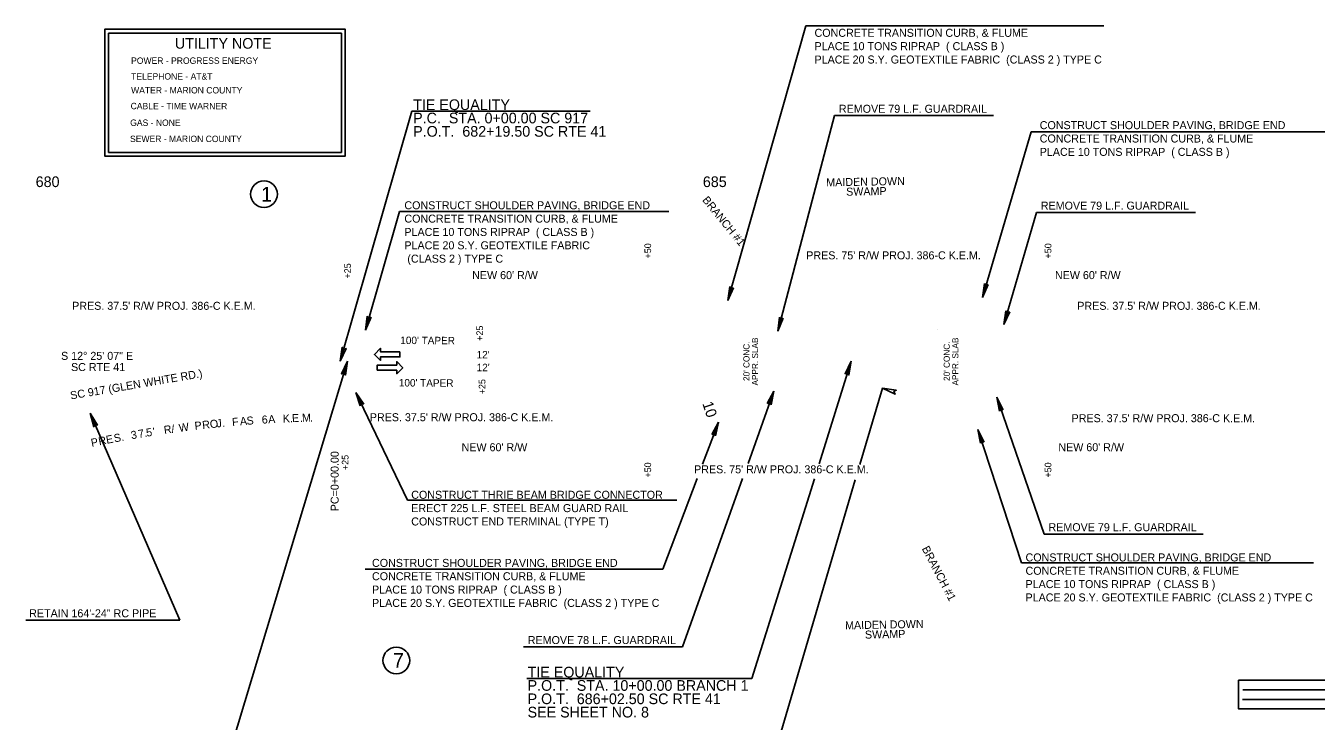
# Model space of a CAD drawing. Extents: x 2522404 to 2525275, y 885432 to 893540.
# Drawn here: x 2523396 to 2524364, y 888336 to 888857 of the extents above; entities that cross this region are included whole.
import ezdxf

# ---------------------------------------------------------------- set-up
doc = ezdxf.new("R2010")
doc.units = 0
for name, color, linetype in [('Default', 7, 'Continuous'), ('RD_DDB_Profile_EX', 7, 'Continuous'), ('RD_DDB_Profile_Lbl', 7, 'Continuous'), ('RD_DDB_StaTX', 7, 'Continuous'), ('RD_EV_JW', 7, 'Continuous'), ('RD_EX_H2O', 7, 'Continuous'), ('RD_EX_Misc', 7, 'Continuous'), ('RD_HC_Cl', 7, 'Continuous'), ('RD_HY_TX1', 7, 'Continuous'), ('RD_PD_Final_LnLine', 7, 'Continuous'), ('RD_PD_RW_TX', 7, 'Continuous'), ('RD_SHT_IplotShp', 7, 'Continuous'), ('RD_SHT_MnGrid', 7, 'Continuous'), ('RD_Sketch1', 7, 'Continuous')]:
    doc.layers.add(name, color=color, linetype=linetype)

# ---------------------------------------------------------------- blocks, each defined once
blk = doc.blocks.new('ah_')
at = {"layer": 'Default'}
blk.add_lwpolyline([(0, 0), (-1.45, -10.39), (0.04, -8.79), (1.55, -10.38)], close=True, dxfattribs=at)
blk = doc.blocks.new('ah4')
at = {"layer": 'Default', "rotation": -90.00000000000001}
blk.add_blockref('ah_', (0, 0), dxfattribs=at)
blk = doc.blocks.new('AH4_')
at = {"layer": 'Default'}
blk.add_lwpolyline([(0, 0), (-10.39, 1.5), (-8.79, 0), (-10.39, -1.5)], close=True, dxfattribs=at)
blk = doc.blocks.new('AH')
at = {"layer": 'Default'}
blk.add_lwpolyline([(0, 0), (-10.39, 1.5), (-8.79, 0), (-10.39, -1.5)], close=True, dxfattribs=at)

msp = doc.modelspace()

# ---------------------------------------------------------------- linework, layer by layer
at = {"layer": 'Default'}
for points in [[(2523676.88, 888612.66), (2523676.88, 888608.84), (2523662.27, 888608.84), (2523662.27, 888606.25), (2523657.77, 888610.75), (2523662.27, 888615.26), (2523662.27, 888612.66)], [(2523659.82, 888598.85), (2523659.82, 888602.67), (2523674.43, 888602.67), (2523674.43, 888605.26), (2523678.93, 888600.76), (2523674.43, 888596.25), (2523674.43, 888598.85)], [(2524305.29, 888366.47), (2524497.8, 888366.47), (2524497.8, 888345.08), (2524305.29, 888345.08)]]:
    msp.add_lwpolyline(points, close=True, dxfattribs=at)
at = {"layer": 'RD_DDB_StaTX'}
for p, q in [((2523922.69, 888651.1), (2523981.2, 888856.99)), ((2524204.41, 888856.99), (2523981.2, 888856.99)), ((2523960.05, 888628.2), (2524002.59, 888789.64)), ((2524113.39, 888653.47), (2524150.02, 888777.41)), ((2524373.22, 888777.41), (2524150.02, 888777.41)), ((2523676.58, 888717.91), (2523650.96, 888628.97)), ((2523878.52, 888717.91), (2523676.58, 888717.91)), ((2524129.55, 888633.06), (2524153.92, 888717.04)), ((2523924.09, 888661.5), (2523922.69, 888651.1)), ((2523924.09, 888661.5), (2523922.69, 888651.1)), ((2523922.69, 888651.1), (2523926.97, 888660.68)), ((2523922.69, 888651.1), (2523926.97, 888660.68)), ((2523925.09, 888659.55), (2523924.09, 888661.5)), ((2523925.09, 888659.55), (2523924.09, 888661.5)), ((2523926.97, 888660.68), (2523925.09, 888659.55)), ((2523926.97, 888660.68), (2523925.09, 888659.55)), ((2524114.89, 888663.85), (2524113.39, 888653.47)), ((2524114.89, 888663.85), (2524113.39, 888653.47)), ((2524113.39, 888653.47), (2524117.77, 888663)), ((2524113.39, 888653.47), (2524117.77, 888663)), ((2524115.88, 888661.89), (2524114.89, 888663.85)), ((2524115.88, 888661.89), (2524114.89, 888663.85)), ((2524117.77, 888663), (2524115.88, 888661.89)), ((2524117.77, 888663), (2524115.88, 888661.89)), ((2523652.39, 888639.36), (2523650.96, 888628.97)), ((2523652.39, 888639.36), (2523650.96, 888628.97)), ((2523653.39, 888637.41), (2523652.39, 888639.36)), ((2523653.39, 888637.41), (2523652.39, 888639.36)), ((2524131, 888643.46), (2524129.55, 888633.06)), ((2524131, 888643.46), (2524129.55, 888633.06)), ((2524129.55, 888633.06), (2524133.88, 888642.62)), ((2524129.55, 888633.06), (2524133.88, 888642.62)), ((2524132, 888641.5), (2524131, 888643.46)), ((2524132, 888641.5), (2524131, 888643.46)), ((2524133.88, 888642.62), (2524132, 888641.5)), ((2524133.88, 888642.62), (2524132, 888641.5)), ((2523650.96, 888628.97), (2523655.27, 888638.53)), ((2523650.96, 888628.97), (2523655.27, 888638.53)), ((2523655.27, 888638.53), (2523653.39, 888637.41)), ((2523655.27, 888638.53), (2523653.39, 888637.41)), ((2523961.25, 888638.63), (2523960.05, 888628.2)), ((2523961.25, 888638.63), (2523960.05, 888628.2)), ((2523960.05, 888628.2), (2523964.14, 888637.86)), ((2523960.05, 888628.2), (2523964.14, 888637.86)), ((2523962.29, 888636.7), (2523961.25, 888638.63)), ((2523962.29, 888636.7), (2523961.25, 888638.63)), ((2523964.14, 888637.86), (2523962.29, 888636.7)), ((2523964.14, 888637.86), (2523962.29, 888636.7)), ((2523682.46, 888501.41), (2523643.89, 888582.12)), ((2523643.89, 888582.12), (2523647.02, 888572.11)), ((2523649.72, 888573.4), (2523643.89, 888582.12)), ((2523643.89, 888582.12), (2523647.02, 888572.11)), ((2523649.72, 888573.4), (2523643.89, 888582.12)), ((2523957.1, 888583.12), (2523937.78, 888529.02)), ((2523957.1, 888583.12), (2523952.21, 888573.83)), ((2523957.1, 888583.12), (2523952.21, 888573.83)), ((2523955.04, 888572.83), (2523957.1, 888583.12)), ((2523955.04, 888572.83), (2523957.1, 888583.12)), ((2524038.47, 888585.31), (2524021.59, 888528.18)), ((2523647.02, 888572.11), (2523647.68, 888574.2)), ((2523647.02, 888572.11), (2523647.68, 888574.2)), ((2523647.68, 888574.2), (2523649.72, 888573.4)), ((2523647.68, 888574.2), (2523649.72, 888573.4)), ((2523952.21, 888573.83), (2523954.16, 888574.84)), ((2523952.21, 888573.83), (2523954.16, 888574.84)), ((2523954.16, 888574.84), (2523955.04, 888572.83)), ((2523954.16, 888574.84), (2523955.04, 888572.83)), ((2524124.22, 888578.58), (2524159.68, 888476.02)), ((2524124.22, 888578.58), (2524126.2, 888568.27)), ((2524129.04, 888569.25), (2524124.22, 888578.58)), ((2524124.22, 888578.58), (2524126.2, 888568.27)), ((2524129.04, 888569.25), (2524124.22, 888578.58)), ((2524126.2, 888568.27), (2524127.1, 888570.27)), ((2524126.2, 888568.27), (2524127.1, 888570.27)), ((2524127.1, 888570.27), (2524129.04, 888569.25)), ((2524127.1, 888570.27), (2524129.04, 888569.25)), ((2523915.5, 888559.62), (2523903.73, 888528.44)), ((2523915.59, 888559.85), (2523910.52, 888550.66)), ((2523915.59, 888559.85), (2523910.52, 888550.66)), ((2523913.32, 888549.61), (2523915.59, 888559.85)), ((2523913.32, 888549.61), (2523915.59, 888559.85)), ((2524110.05, 888554.4), (2524142.77, 888454.59)), ((2524110.05, 888554.4), (2524111.86, 888544.06)), ((2524114.71, 888545), (2524110.05, 888554.4)), ((2524110.05, 888554.4), (2524111.86, 888544.06)), ((2524114.71, 888545), (2524110.05, 888554.4)), ((2523910.52, 888550.66), (2523912.48, 888551.63)), ((2523910.52, 888550.66), (2523912.48, 888551.63)), ((2523912.48, 888551.63), (2523913.32, 888549.61)), ((2523912.48, 888551.63), (2523913.32, 888549.61)), ((2524111.86, 888544.06), (2524112.79, 888546.05)), ((2524111.86, 888544.06), (2524112.79, 888546.05)), ((2524112.79, 888546.05), (2524114.71, 888545)), ((2524112.79, 888546.05), (2524114.71, 888545)), ((2523899.67, 888517.67), (2523874.02, 888449.71)), ((2523933.73, 888517.68), (2523888.63, 888391.44)), ((2524018.16, 888516.59), (2523961.24, 888323.94)), ((2523884.39, 888501.41), (2523682.46, 888501.41)), ((2523874.02, 888449.71), (2523650.82, 888449.71)), ((2524361.62, 888454.59), (2524142.77, 888454.59))]:
    msp.add_line(p, q, dxfattribs=at)
for points in [[(2524121.81, 888789.64), (2524002.59, 888789.64)], [(2524273.13, 888717.04), (2524153.92, 888717.04)], [(2524278.9, 888476.02), (2524159.68, 888476.02)], [(2523888.63, 888391.44), (2523769.42, 888391.44)]]:
    msp.add_lwpolyline(points, dxfattribs=at)
at = {"layer": 'RD_EV_JW'}
msp.add_line((2524308.27, 888351.99), (2524383.17, 888351.99), dxfattribs=at)
at = {"layer": 'RD_EX_H2O'}
msp.add_line((2524382.98, 888359.41), (2524308.55, 888359.41), dxfattribs=at)
at = {"layer": 'RD_EX_Misc'}
for points in [[(2523471.74, 888759.33), (2523455.67, 888759.33), (2523455.67, 888854.37), (2523635.89, 888854.37), (2523635.89, 888759.33), (2523471.74, 888759.33)], [(2523474.65, 888762.08), (2523458.57, 888762.08), (2523458.57, 888851.46), (2523632.99, 888851.46), (2523632.99, 888762.08), (2523474.65, 888762.08)]]:
    msp.add_lwpolyline(points, dxfattribs=at)
for centre in [(2523575, 888730.79), (2523674.17, 888381.31)]:
    msp.add_circle(centre, 10, dxfattribs=at)
at = {"layer": 'RD_HC_Cl'}
msp.add_line((2524080.12, 888629.12), (2524080.12, 888629.12), dxfattribs=at)
at = {"layer": 'RD_HY_TX1'}
for points in [[(2523444.63, 888566.61), (2523511.85, 888411.59)], [(2523511.85, 888411.59), (2523396.48, 888411.59)]]:
    msp.add_lwpolyline(points, dxfattribs=at)
at = {"layer": 'RD_PD_RW_TX'}
for p, q in [((2523632.12, 888605.62), (2523685.82, 888793.08)), ((2523685.82, 888793.08), (2523819.36, 888793.08)), ((2524015.12, 888605.61), (2523990.95, 888528.61)), ((2523987.47, 888517.53), (2523940.49, 888367.86)), ((2523771.89, 888367.86), (2523940.49, 888367.86))]:
    msp.add_line(p, q, dxfattribs=at)
at = {"layer": 'RD_SHT_MnGrid'}
msp.add_line((2523546.05, 888301.87), (2523637.62, 888605.62), dxfattribs=at)

# ---------------------------------------------------------------- block references
at = {"layer": 'RD_HY_TX1', "rotation": 113.16953356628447}
msp.add_blockref('ah4', (2523444.63, 888566.61), dxfattribs=at)
at = {"layer": 'RD_PD_Final_LnLine'}
for p, rotation in [((2523632.12, 888605.62), -106.25802464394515), ((2523637.62, 888605.62), 72.95136999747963), ((2524015.12, 888605.61), 72.29836329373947)]:
    msp.add_blockref('AH4_', p, dxfattribs=dict(at, rotation=rotation))
at = {"layer": 'RD_PD_Final_LnLine', "yscale": -0.9999999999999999, "rotation": 163.81043232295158}
msp.add_blockref('AH', (2524038.47, 888585.31), dxfattribs=at)

# ---------------------------------------------------------------- texts
at = {"layer": 'RD_DDB_Profile_EX'}
for s, height, rotation, p in [('680', 8, 360, (2523403.89, 888736.12)), ('685', 8, 360, (2523903.92, 888736.12)), ("20' CONC.", 4.605, 90, (2523938.85, 888590.79)), ('APPR. SLAB', 4.605, 90, (2523945.3, 888587.39)), ("20' CONC.", 4.605, 90, (2524088.95, 888590.79)), ('APPR. SLAB', 4.605, 90, (2524095.4, 888587.39)), ('10', 8, 288.69992, (2523903.39, 888573.91))]:
    msp.add_text(s, height=height, rotation=rotation, dxfattribs=at).set_placement(p)
at = {"layer": 'RD_DDB_Profile_Lbl'}
for s, p in [('1', (2523572.87, 888725.29)), ('7', (2523671.65, 888375.81))]:
    msp.add_text(s, height=11, dxfattribs=at).set_placement(p)
at = {"layer": 'RD_DDB_StaTX'}
for s, p in [('CONCRETE TRANSITION CURB, & FLUME', (2523987.6, 888848.73)), ('PLACE 10 TONS RIPRAP  ( CLASS B )', (2523987.6, 888838.73)), ('PLACE 20 S.Y. GEOTEXTILE FABRIC  (CLASS 2 ) TYPE C', (2523987.6, 888828.73)), ('REMOVE 79 L.F. GUARDRAIL', (2524005.86, 888791.81)), ('CONSTRUCT SHOULDER PAVING, BRIDGE END', (2524156.38, 888779.52)), ('CONCRETE TRANSITION CURB, & FLUME', (2524156.38, 888769.52)), ('PLACE 10 TONS RIPRAP  ( CLASS B )', (2524156.38, 888759.52)), ('CONSTRUCT SHOULDER PAVING, BRIDGE END', (2523680.21, 888719.47)), ('REMOVE 79 L.F. GUARDRAIL', (2524157.19, 888719.2)), ('CONCRETE TRANSITION CURB, & FLUME', (2523680.21, 888709.47)), ('PLACE 10 TONS RIPRAP  ( CLASS B )', (2523680.21, 888699.47)), ('PLACE 20 S.Y. GEOTEXTILE FABRIC ', (2523680.21, 888689.47)), (' (CLASS 2 ) TYPE C', (2523680.21, 888679.47)), ('CONSTRUCT THRIE BEAM BRIDGE CONNECTOR', (2523685.33, 888502.49)), ('ERECT 225 L.F. STEEL BEAM GUARD RAIL', (2523685.33, 888492.49)), ('CONSTRUCT END TERMINAL (TYPE T)', (2523685.33, 888482.49)), ('REMOVE 79 L.F. GUARDRAIL', (2524162.96, 888478.18)), ('CONSTRUCT SHOULDER PAVING, BRIDGE END', (2523655.95, 888451.43)), ('CONSTRUCT SHOULDER PAVING, BRIDGE END', (2524145.74, 888455.54)), ('CONCRETE TRANSITION CURB, & FLUME', (2523655.95, 888441.43)), ('CONCRETE TRANSITION CURB, & FLUME', (2524145.74, 888445.54)), ('PLACE 10 TONS RIPRAP  ( CLASS B )', (2523655.95, 888431.43)), ('PLACE 10 TONS RIPRAP  ( CLASS B )', (2524145.74, 888435.54)), ('PLACE 20 S.Y. GEOTEXTILE FABRIC  (CLASS 2 ) TYPE C', (2523655.95, 888421.43)), ('PLACE 20 S.Y. GEOTEXTILE FABRIC  (CLASS 2 ) TYPE C', (2524145.74, 888425.54)), ('REMOVE 78 L.F. GUARDRAIL', (2523772.69, 888393.6))]:
    msp.add_text(s, height=6, dxfattribs=at).set_placement(p)
for s, p in [("100' TAPER", (2523677.12, 888618.51)), ("12'", (2523734.33, 888607.74)), ("12'", (2523734.36, 888598.13)), ("100' TAPER", (2523676.03, 888586.68))]:
    msp.add_text(s, height=5.6, rotation=359.58606, dxfattribs=at).set_placement(p)
at = {"layer": 'RD_EX_Misc'}
for s, height, p in [('UTILITY NOTE', 8, (2523508.19, 888839.83)), ('POWER - PROGRESS ENERGY', 4.8, (2523475.39, 888828.48)), ('TELEPHONE - AT&T', 4.8, (2523475.39, 888816.68)), ('WATER - MARION COUNTY', 4.8, (2523475.39, 888806.29)), ('CABLE - TIME WARNER', 4.8, (2523475.04, 888794.45)), ('GAS - NONE', 4.8, (2523474.7, 888781.95)), ('SEWER - MARION COUNTY', 4.8, (2523474.59, 888769.84))]:
    msp.add_text(s, height=height, dxfattribs=at).set_placement(p)
at = {"layer": 'RD_HC_Cl'}
for s, height, rotation, p in [('TIE EQUALITY', 8, 360, (2523686.78, 888793.87)), ('P.C.  STA. 0+00.00 SC 917', 8, 360, (2523686.78, 888783.87)), ('P.O.T.  682+19.50 SC RTE 41', 8, 360, (2523686.78, 888773.87)), ('MAIDEN DOWN', 6, 1.09953, (2523996.46, 888736.6)), ('SWAMP', 6, 1.09953, (2524011.34, 888729.63)), ('BRANCH #1', 6, 309.1987, (2523903.12, 888726.23)), ('S 12%%d 25\' 07" E', 6, 360, (2523422.91, 888606.62)), ('SC RTE 41', 6, 360, (2523430.36, 888598.22)), ('SC 917 (GLEN WHITE RD.)', 6, 9.6249, (2523430.31, 888576.9)), ('PC=0+00.00', 6, 90.00001, (2523630.96, 888493.13)), ('BRANCH #1', 6, 297.53181, (2524067.83, 888465.16)), ('MAIDEN DOWN', 6, 1.09953, (2524010.55, 888404.62)), ('SWAMP', 6, 1.09953, (2524025.43, 888397.66)), ('TIE EQUALITY', 8, 360, (2523772.55, 888368.57)), ('P.O.T.  STA. 10+00.00 BRANCH 1', 8, 360, (2523772.55, 888358.57)), ('P.O.T.  686+02.50 SC RTE 41', 8, 360, (2523772.55, 888348.57)), ('SEE SHEET NO. 8', 8, 360, (2523772.55, 888338.57))]:
    msp.add_text(s, height=height, rotation=rotation, dxfattribs=at).set_placement(p)
at = {"layer": 'RD_HY_TX1'}
msp.add_text('RETAIN 164\'-24" RC PIPE', height=6, dxfattribs=at).set_placement((2523399.02, 888413.67))
at = {"layer": 'RD_SHT_IplotShp'}
for s, height, rotation, p in [('+50', 5, 90, (2523865.12, 888682.62)), ("PRES. 75' R/W PROJ. 386-C K.E.M.", 6, 360, (2523981.39, 888681.95)), ('+50', 5, 90, (2524165.12, 888682.62)), ("PRES. 37.5' R/W PROJ. 386-C K.E.M.", 6, 360, (2523431.23, 888644.12)), ("PRES. 37.5' R/W PROJ. 386-C K.E.M.", 6, 360, (2524184.52, 888644.12)), ('+25', 5, 90, (2523739.17, 888620.91)), ('+25', 5, 90, (2523740.94, 888580.83)), ('O', 6, 5.96551, (2523534.69, 888555.39)), ('J', 6, 5.65225, (2523539.64, 888555.91)), ('F', 6, 4.91636, (2523551.27, 888557.02)), ('A', 6, 4.54399, (2523557.16, 888557.53)), ('S', 6, 4.23072, (2523562.12, 888557.92)), ('6', 6, 3.51257, (2523573.5, 888558.73)), ('A', 6, 3.21113, (2523578.28, 888559.03)), ('K', 6, 2.52253, (2523589.2, 888559.61)), ('E', 6, 2.09105, (2523596.04, 888559.91)), ('M', 6, 1.6182, (2523603.55, 888560.17)), ("PRES. 37.5' R/W PROJ. 386-C K.E.M.", 6, 360, (2523654.31, 888560.62)), ("PRES. 37.5' R/W PROJ. 386-C K.E.M.", 6, 360, (2524180.25, 888559.89)), ('3', 6, 9.71289, (2523475.77, 888547.09)), ('7', 6, 9.37007, (2523481.13, 888548.01)), ('5', 6, 8.98588, (2523487.15, 888549)), ("'", 6, 8.66079, (2523492.25, 888549.81)), ('R', 6, 8.1436, (2523500.37, 888551.03)), ('/', 6, 7.78305, (2523506.04, 888551.84)), ('W', 6, 7.43432, (2523511.53, 888552.59)), ('P', 6, 6.68662, (2523523.31, 888554.09)), ('R', 6, 6.32606, (2523529, 888554.76)), ('.', 6, 5.39217, (2523543.75, 888556.32)), ('.', 6, 2.19153, (2523594.45, 888559.84)), ('.', 6, 1.71868, (2523601.95, 888560.12)), ('.', 6, 1.24582, (2523609.46, 888560.34)), ('P', 6, 11.625, (2523445.94, 888541.37)), ('R', 6, 11.26445, (2523451.55, 888542.52)), ('E', 6, 10.9039, (2523457.17, 888543.64)), ('S', 6, 10.53152, (2523462.98, 888544.76)), ('.', 6, 10.1887, (2523468.33, 888545.76)), ('.', 6, 9.08636, (2523485.58, 888548.74)), ('+50', 5, 90, (2523865.12, 888518.42)), ("PRES. 75' R/W PROJ. 386-C K.E.M.", 6, 360, (2523897.33, 888521.58)), ('+50', 5, 90, (2524165.12, 888518.42))]:
    msp.add_text(s, height=height, rotation=rotation, dxfattribs=at).set_placement(p)
at = {"layer": 'RD_Sketch1'}
for s, height, rotation, p in [('+25', 5, 90, (2523640.12, 888667.62)), ("NEW 60' R/W", 6, 360, (2523731.01, 888667.12)), ("NEW 60' R/W", 6, 360, (2524167.79, 888667.12)), ("NEW 60' R/W", 6, 360, (2523723.08, 888538.12)), ("NEW 60' R/W", 6, 360, (2524170.34, 888538.12)), ('+25', 5, 90, (2523638.32, 888524.04))]:
    msp.add_text(s, height=height, rotation=rotation, dxfattribs=at).set_placement(p)

doc.saveas('drawing.dxf')
